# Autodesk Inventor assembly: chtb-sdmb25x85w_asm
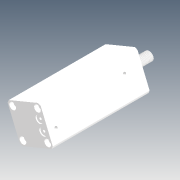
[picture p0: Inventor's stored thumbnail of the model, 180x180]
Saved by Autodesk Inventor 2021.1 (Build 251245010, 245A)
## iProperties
Company: Microsoft
Created: 2018-05
Part Number: chtb-sdmb25x85w_asm
Description: STEP AP214
Document SubType Name: Assembly
Designer: user
Title: chtb-sdmb25x85w_asm.STEP
Author: Windows
Revision Number: ÈÎºÎ
Sending System: SolidWorks 2015
Preprocessor: SwSTEP 2.0
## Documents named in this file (4)
- D:\Vault_2016\Projekty\Clamptek\Hydraulic\CHTB\CHTB-25\Inventor\chtb-sdmb25x85w\chtb-sdmb25x85w_asm.iam
- D:\Vault_2016\Projekty\Clamptek\Hydraulic\CHTB\CHTB-25\Inventor\chtb-sdmb25x85w\CHTB-25QG.ipt
- D:\Vault_2016\Projekty\Clamptek\Hydraulic\CHTB\CHTB-25\Inventor\chtb-sdmb25x85w\CHTB-SDMB25X85NBT.ipt
- D:\Vault_2016\Projekty\Clamptek\Hydraulic\CHTB\CHTB-25\Inventor\chtb-sdmb25x85w\CHTB-SDMB25X85WHSG.ipt
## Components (3 placed, 3 different names)
1. CHTB-25QG_1
2. CHTB-SDMB25X85NBT_2
3. CHTB-SDMB25X85WHSG_3
